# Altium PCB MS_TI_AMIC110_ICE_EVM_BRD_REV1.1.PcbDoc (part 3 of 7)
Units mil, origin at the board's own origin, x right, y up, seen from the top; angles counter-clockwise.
Board outline 3464.57 x 2204.72 mil, 8 copper layers (TopLayer - S1 (.GTL), MidLayer1 - S2 (.G1), MidLayer2 - S3 (.G2), MidLayer3 - S4 (.G3), MidLayer4 - S5 (.G4), MidLayer5 - S6 (.G5), MidLayer6 - S7 (.G6), BottomLayer - S8 (.GBL)), stack 58.937 mil thick; 504 components, 369 nets, 1811 pads, 874 vias.
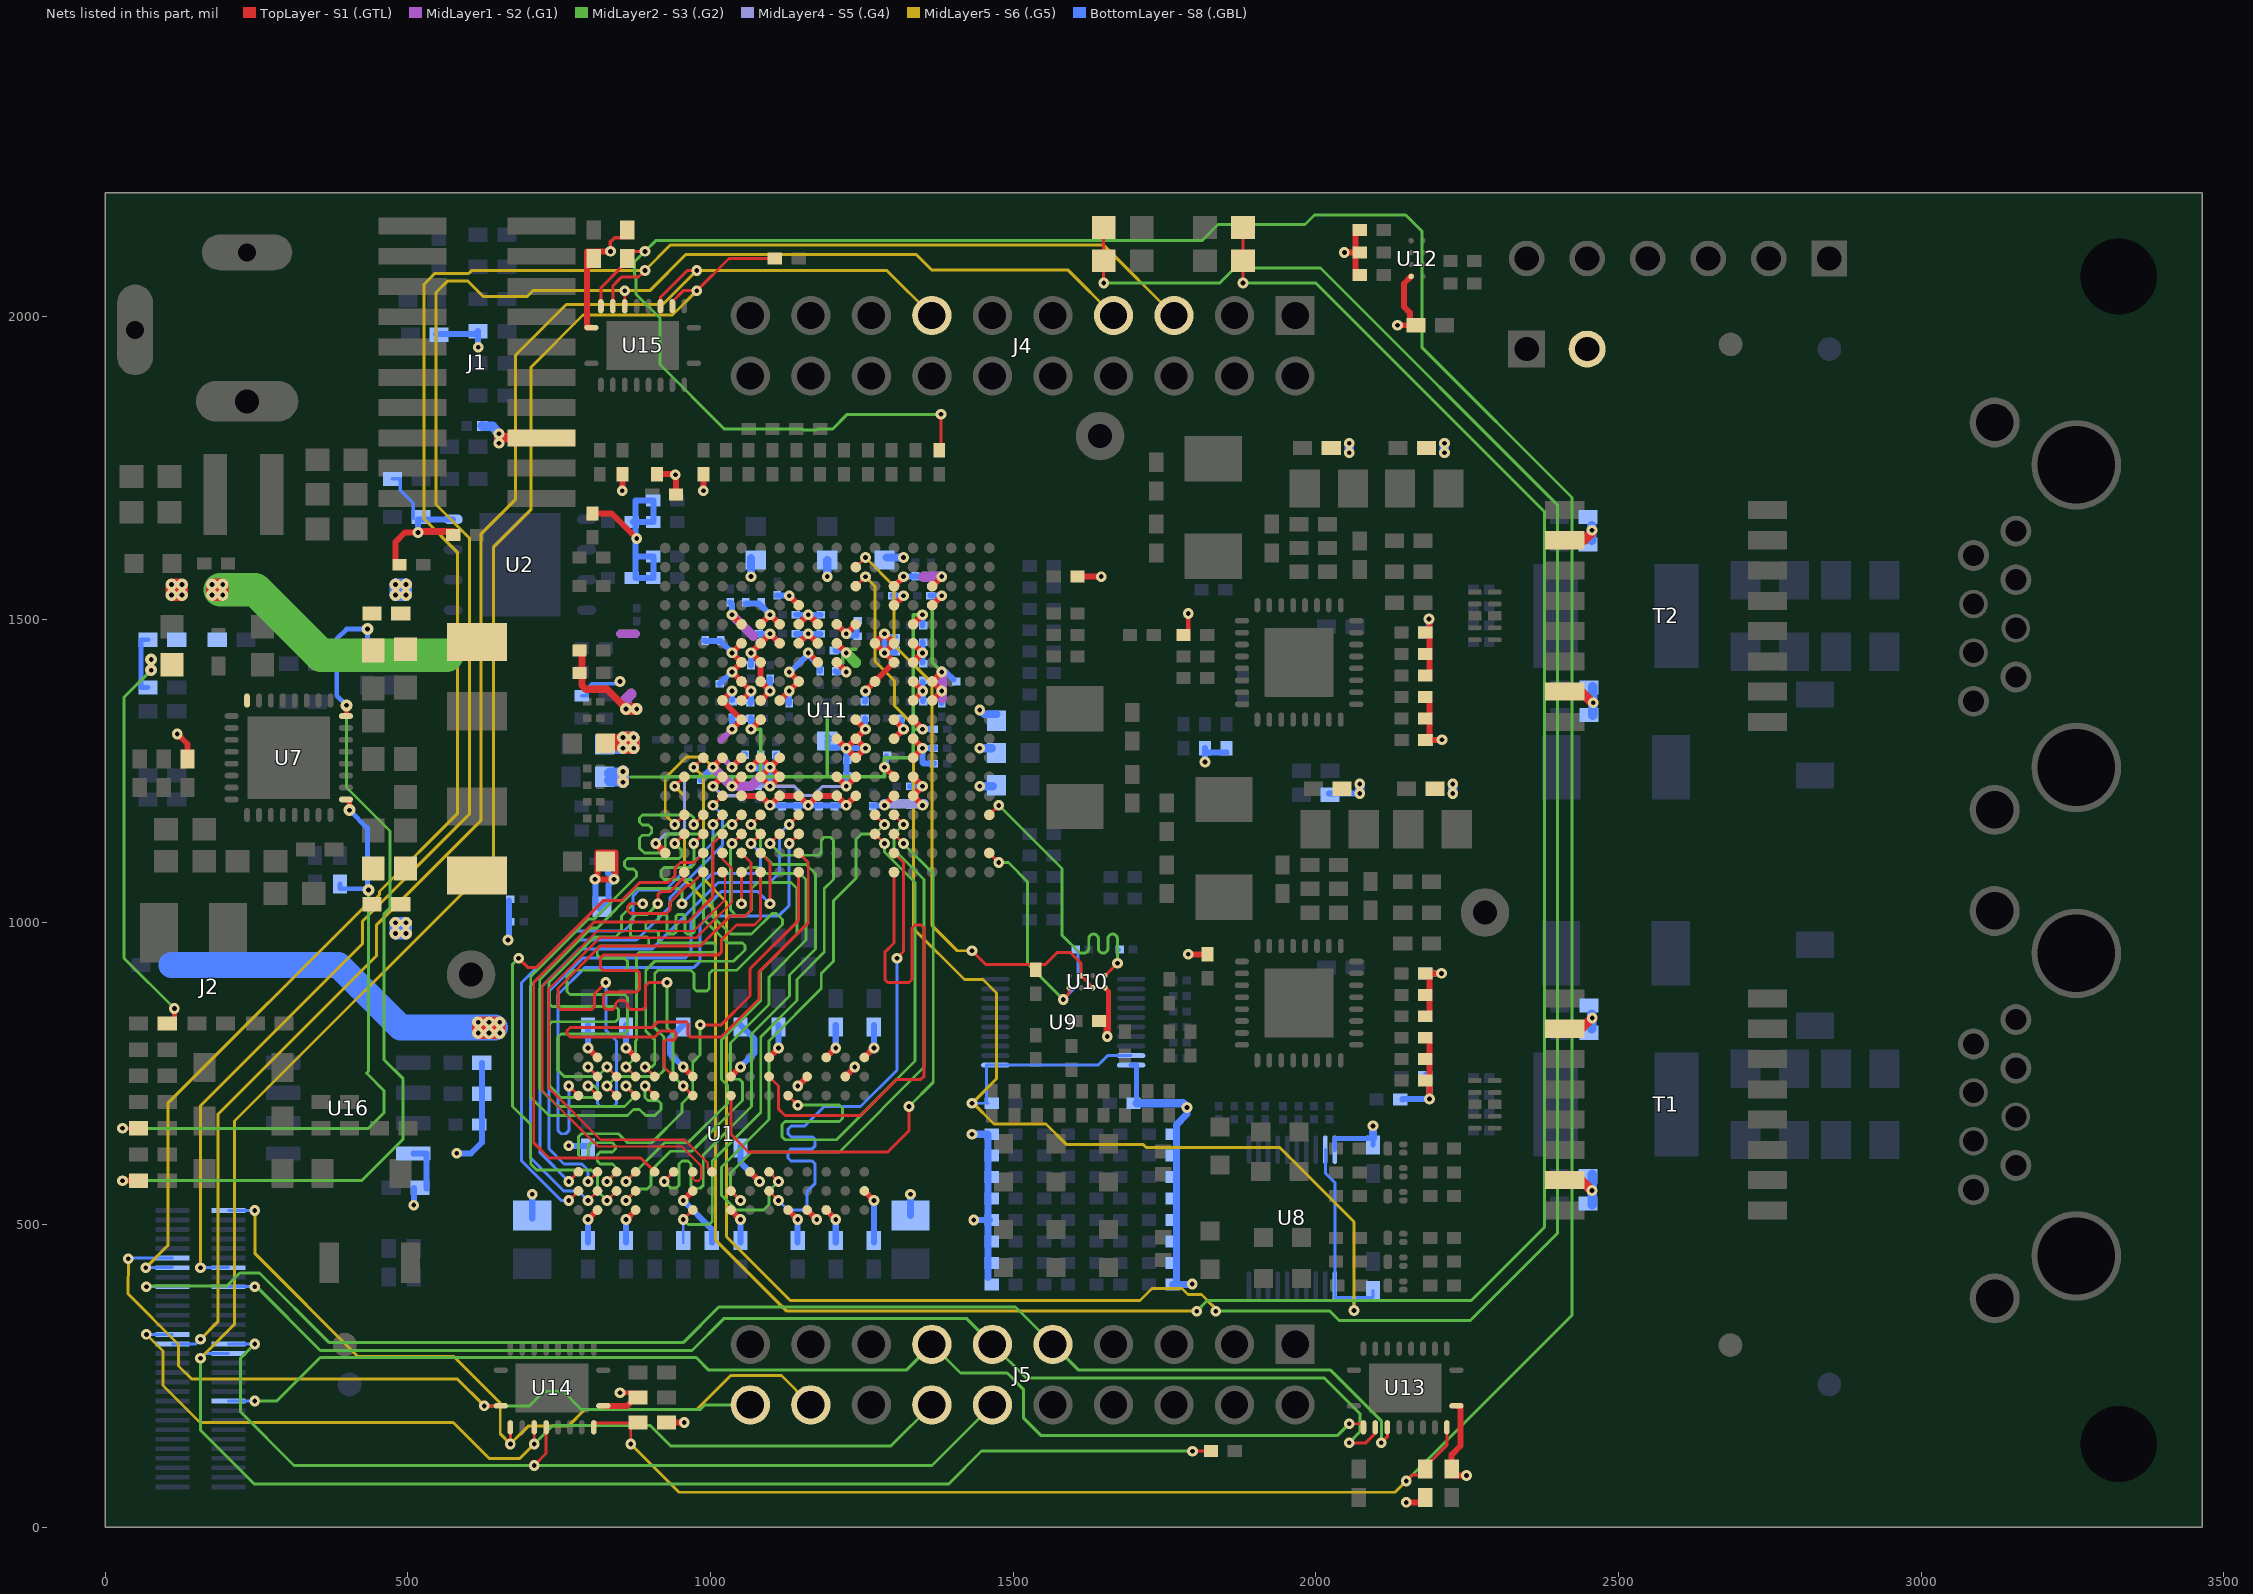
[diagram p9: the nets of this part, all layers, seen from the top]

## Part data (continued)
U16: "256 kb I2C CMOS Serial EEPROM, SOIC-8", Manufacturer="ON Semiconductor", Supplier Part Number 1=CAT24C256WI-GT3OSCT-ND
Y1 Y2 Y3: "Crystal, 25 MHz, 18 pF, SMD", Frequency="25 MHz", Frequency Stability=±20ppm, Manufacturer="CTS ELECTRONIC COMPONENTS", Supplier Part Number 1=445123D25M00000
ZZ1: library part AssemblyNoteLabel, Alternate Manufacturer=-
ZZ2 ZZ3 ZZ4: library part AssemblyNote, Alternate Manufacturer=-

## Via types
v1: diameter 17.72, hole 7.87, TopLayer - S1 (.GTL) to BottomLayer - S8 (.GBL), 746 vias
v2: diameter 19.68, hole 7.87, TopLayer - S1 (.GTL) to BottomLayer - S8 (.GBL), 128 vias

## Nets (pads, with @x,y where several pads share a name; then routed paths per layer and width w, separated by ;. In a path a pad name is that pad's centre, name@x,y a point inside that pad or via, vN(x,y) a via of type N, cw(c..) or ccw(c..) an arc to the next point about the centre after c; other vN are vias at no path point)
1V1: C147.1 C148.1 C149.1 C150.1 C151.1 C152.1 C153.1 C154.1 C155.1 C156.1 C157.1 C158.1 C159.1 C160.1 C161.1 C162.1 C163.1 C164.1 C165.1 C166.1 C167.1 R77.2 U11.A2 U11.D6 U11.F6 U11.F7 U11.F10 U11.F11 U11.F12 U11.F13 U11.G6 U11.G7 U11.G10 U11.G13 U11.H11 U11.H13 U11.J12 U11.J13 U11.K6 U11.K8 U11.K12 U11.L6 U11.L7 U11.L8 U11.L9 U11.M11 U11.M13 U11.N8 U11.N9 U11.N12 U11.N13 | length 2319.2
  TopLayer - S1 (.GTL) w10: v1(1003.94,1224.41) U11.D6@1019.68,1240.16 ; v1(1066.93,1255.91) U11.F7@1082.68,1271.65 v1(1098.43,1255.91) ; U11.F11@1082.68,1397.64 1085.63,1394.67 v1(1098.42,1381.88) U11.F10@1082.68,1366.14 U11.F10@1085.63,1369.11 ; U11.F11@1085.63,1394.68 U11.F11@1082.68,1397.64 U11.F12@1082.68,1429.13 v1(1066.93,1444.88) 1082.66,1460.64 v1(1098.43,1476.38) U11.G13@1114.17,1460.63 ; U11.G7@1114.17,1271.65 v1(1098.43,1255.91) ; U11.G10@1114.18,1366.16 v1(1129.92,1381.89) 1145.67,1397.64 v1(1129.92,1413.39) ; U11.H13@1145.68,1460.64 v1(1161.42,1476.38) U11.J13@1177.17,1460.63 ; v1(1161.42,1444.88) U11.J12@1177.17,1429.13 ; U11.K6@1208.66,1240.16 v1(1224.41,1224.41) U11.L6@1240.16,1240.16 ; U11.K8@1208.66,1303.15 v1(1224.41,1287.4) ; U11.K12@1208.66,1429.13 v1(1224.41,1413.39) ; U11.L9@1240.16,1334.65 v1(1255.91,1318.9) U11.L8@1240.16,1303.15 ; v1(1255.91,1381.89) U11.M11@1271.65,1397.64 U11.N12@1303.15,1429.13 v1(1287.4,1444.88) ; U11.N8@1303.15,1303.15 v1(1318.9,1318.9) U11.N9@1303.15,1334.65 ; v1(1098.43,1255.91) U11.G6@1114.17,1240.16 v1(1098.43,1224.41) U11.F6@1082.68,1240.16 v1(1098.43,1255.91) ; v1(1224.41,1287.4) U11.L8@1240.16,1303.15 ; v1(1224.41,1287.4) U11.L7@1240.16,1271.65 v1(1255.91,1287.4) U11.L8@1240.16,1303.15 ; v1(1287.4,1444.88) U11.M13@1271.65,1460.63 v1(1287.4,1476.38) U11.N13@1303.15,1460.63 v1(1287.4,1444.88)
  TopLayer - S1 (.GTL) w12: v1(909.45,1129.92) U11.A2@925.2,1114.17
  TopLayer - S1 (.GTL) w19.68: C162.1@826.77,1297.24 826.77,1301.18 855.31,1301.18 855.31,1293.31 C162.1@828.74,1293.31 ; v2(855.31,1287.4) v2(855.31,1305.12) v2(873.03,1305.12) v2(873.03,1287.4) v2(855.31,1287.4)
  MidLayer1 - S2 (.G1) w19.68: v2(873.03,1287.4) v2(873.03,1305.12)
  MidLayer4 - S5 (.G4) w4.92: v1(909.45,1129.92) 925.2,1145.67 947.83,1145.67 957.18,1155.02 957.18,1235.84 ; 1138.36,1224.41 1153.62,1209.15 1169.78,1209.15 1185.04,1224.41 v1(1224.41,1224.41)
  MidLayer4 - S5 (.G4) w5.91: v1(1003.94,1224.41) 1019.69,1208.66 1042.74,1208.66 1058.49,1224.41 v1(1098.43,1224.41) 1138.36,1224.41
  BottomLayer - S8 (.GBL) w9.84: C164.1@1066.93,1424.41 v1(1066.93,1444.88) ; C165.1@1077.95,1476.38 v1(1098.43,1476.38) ; C149.1@1078.74,1227.36 v1@1097.44,1227.36 ; v1(1098.43,1224.41) v1(1098.43,1255.91) ; v1(1098.42,1381.88) C163.1@1098.43,1402.36 ; C152.1@1129.92,1361.42 v1(1129.92,1381.89) ; v1(1129.92,1413.39) 1131.9,1413.4 1161.42,1442.91 1161.42,1441.93 1181.1,1422.24 C153.1@1181.1,1414.57 ; C166.1@1140.94,1476.38 C167.1@1181.89,1476.38 ; C148.1@1192.91,1299.21 1192.91,1288.39 1223.43,1288.39 v1(1224.41,1287.4) ; C148.1@1192.92,1307.4 C148.1@1197.17,1303.15 ; C154.1@1206.69,1414.57 1207.87,1413.39 v1(1224.41,1413.39) ; v1(1224.41,1224.41) v1(1224.41,1287.4) ; C156.1@1255.12,1336.61 1255.12,1319.69 v1(1255.91,1318.9) ; C155.1@1255.12,1364.17 1255.91,1364.96 v1(1255.91,1381.89) ; v1(1255.91,1287.4) v1(1224.41,1287.4) ; C158.1@1305.12,1446.06 1304.92,1445.87 1288.39,1445.87 v1(1287.4,1444.88) v1(1287.4,1476.38) 1292.32,1471.46 C157.1@1305.12,1471.46 ; v1@1315.94,1318.9 C159.1@1315.94,1334.65
  BottomLayer - S8 (.GBL) w10: 1082.68,1255.91 C150.1@1082.68,1276.38 ; v1(1098.43,1255.91) 1108.27,1265.75 C151.1@1108.27,1276.38
  BottomLayer - S8 (.GBL) w13.78: v1(1066.93,1255.91) v1(1098.43,1255.91)
  BottomLayer - S8 (.GBL) w19.68: C147.1@820.87,1287.4 v2(855.31,1287.4) ; C147.1@820.87,1299.21 v2@855.31,1299.21 ; v2@857.58,1292.32 v2@855.31,1292.32 ; v2(855.31,1287.4) v2@855.31,1292.32 ; v2(855.31,1287.4) v2(873.03,1287.4) v2(873.03,1305.12) v2(855.31,1305.12) v2@855.31,1299.21 ; v2@855.31,1292.32 v2@855.31,1299.21 ; v2(479.33,1540.35) v2(497.05,1540.35) v2(497.05,1558.07) v2(479.33,1558.07) v2(479.33,1540.35)
1V1_EN: C70.1 C71.1 L1.2 R77.1 R78.2 R95.2 U7.8 | length 1521.2
  TopLayer - S1 (.GTL) w7.87: U7.8@397.64,1340.55 398.62,1341.54 v2(398.62,1358.27)
  TopLayer - S1 (.GTL) w9.84: v1(28.54,572.83) R95.2@55.12,572.83
  MidLayer2 - S3 (.G2) w4.92: v1@26.57,572.83 v1(28.54,572.83) 423.23,572.83 492.13,641.73 492.13,741.14 460.63,772.64 460.63,1013.78 470.47,1023.62 470.47,1150.59 398.62,1222.44 v2(398.62,1358.27)
  BottomLayer - S8 (.GBL) w7.87: v2(398.62,1358.27) 382.54,1374.35 382.54,1468.17 398.62,1484.25 v2(433.07,1484.25) R78.2@433.07,1438.98
1V5: C7.1 C8.1 C9.1 C10.1 C11.1 C12.1 C13.1 C14.1 C15.1 C16.1 C17.1 C18.1 C19.1 C20.1 C21.1 C22.1 C136.1 C137.1 C138.1 C139.1 C140.1 C141.1 C142.1 C143.1 C144.1 R34.1 R37.1 R81.2 U1.A1 U1.A8 U1.B2 U1.C1 U1.C9 U1.D2 U1.D9 U1.E9 U1.F1 U1.G7 U1.H2 U1.H9 U1.K2 U1.K8 U1.N1 U1.N9 U1.R1 U1.R9 U11.E5 U11.F5 U11.G5 U11.H5 U11.J5 U11.K5 U11.L5 | length 2836.2
  TopLayer - S1 (.GTL) w10: v1(797.42,508.65) U1.R9@813.17,524.4 ; v1(797.42,792.15) U1.R1@813.17,776.4 ; v1(860.42,508.65) U1.N9@876.17,524.4 ; v1(860.42,792.15) U1.N1@876.17,776.4 ; v1(954.92,540.15) U1.K8@970.67,555.9 ; v1(954.92,760.65) U1.K2@970.67,744.9 ; U1.H9@1033.67,524.4 v1(1049.42,508.65) ; U1.H2@1033.67,744.9 v1(1049.42,760.65) ; U11.E5@1051.18,1208.66 U11.F5@1082.68,1208.66 v1(1098.43,1192.91) U11.G5@1114.17,1208.66 1145.67,1208.66 v1(1161.42,1192.91) U11.J5@1177.17,1208.66 U11.K5@1208.66,1208.66 v1(1224.41,1192.91) U11.L5@1240.16,1208.66 ; U1.G7@1065.17,587.4 v1(1080.92,571.65) ; U1.F1@1096.67,776.4 v1(1112.42,792.15) ; U1.E9@1128.17,524.4 v1(1143.92,508.65) ; v1(1143.92,729.15) U1.D2@1159.67,744.9 ; U1.D9@1159.67,524.4 v1(1175.42,508.65) ; U1.C9@1191.17,524.4 v1(1206.92,508.65) ; U1.C1@1191.17,776.4 v1(1206.92,792.15) ; U1.B2@1222.67,744.9 v1(1238.42,760.65) ; U1.A8@1254.17,555.92 v1(1269.92,540.15) ; U1.A1@1254.17,776.4 v1(1269.92,792.15) ; v1@812.92,1070.4 842.92,1070.4 842.92,1115.16 812.92,1115.16 812.92,1100.39 v1@812.92,1070.4
  TopLayer - S1 (.GTL) w19.68: v2(633.86,816.93) v2(633.86,834.65) ; v2(633.86,816.93) v2(616.14,816.93) v2(616.14,834.65) v2(633.86,834.65) ; v2(633.86,816.93) v2(651.57,816.93) v2(651.57,834.65) v2(633.86,834.65)
  BottomLayer - S8 (.GBL) w9.84: v1(1098.43,1192.91) v1(1161.42,1192.91) 1204.72,1192.91 v1(1224.41,1192.91)
  BottomLayer - S8 (.GBL) w10: v1(665.42,970.4) 667.32,972.3 C143.1@667.32,1035.43 ; C8.1@705.42,510.4 v1(705.42,550.4) ; v1(765.92,630.4) R37.1@797.42,630.4 ; C11.1@797.42,470.4 C11.1@797.42,474.02 v1(797.42,508.65) ; v1(797.42,792.15) C18.1@797.42,826.78 C18.1@797.42,830.4 ; v1@812.92,1070.4 810.04,1067.51 810.04,1029.53 816.93,1022.64 820.08,1025.79 831.69,1037.4 831.69,1062.01 v1(840.55,1070.87) 830.71,1080.71 C142.1@830.71,1100.4 ; C10.1@860.42,470.4 C10.1@860.42,474.02 v1(860.42,508.65) ; v1(860.42,792.15) C17.1@860.42,826.78 C17.1@860.42,830.4 ; v1(954.92,540.15) 1002.17,492.9 C9.1@1002.17,474.02 C9.1@1002.17,470.4 ; v1(954.92,760.65) 932.92,782.65 932.92,808.4 C16.1@954.92,830.4 ; C22.1@1049.42,470.4 C22.1@1049.42,474.02 v1(1049.42,508.65) ; R34.1@1049.42,630.4 R34.1@1049.42,626.78 1049.42,603.15 v1(1080.92,571.65) ; v1(1049.42,760.65) 1072.92,784.15 1072.92,806.9 C15.1@1049.42,830.4 ; v1(1112.42,792.15) C14.1@1112.42,826.78 C14.1@1112.42,830.4 ; C21.1@1143.92,470.4 C21.1@1143.92,474.02 v1(1143.92,508.65) ; C20.1@1206.92,470.4 C20.1@1206.92,474.02 v1(1206.92,508.65) ; v1(1206.92,792.15) C13.1@1206.92,826.78 C13.1@1206.92,830.4 ; C19.1@1269.92,470.4 C19.1@1269.92,474.02 v1(1269.92,540.15) ; v1(1269.92,792.15) C12.1@1269.92,826.78 C12.1@1269.92,830.4
  BottomLayer - S8 (.GBL) w11.81: C7.1@1330.42,515.4 v1(1330.42,550.4)
  BottomLayer - S8 (.GBL) w19.68: v2(633.86,816.93) 633.86,825.79 v2(633.86,834.65) ; v2(633.86,816.93) v2(616.14,816.93) 616.14,825.79 v2(616.14,834.65) v2(633.86,834.65) ; v2(633.86,816.93) v2(651.57,816.93) v2(651.57,834.65) v2(633.86,834.65)
  BottomLayer - S8 (.GBL) w43.31: R81.2@109.25,929.13 384.84,929.13 488.19,825.79 616.14,825.79 633.86,825.79 643.7,825.79
  other v1: 809.06,1070.87
1V8_1: C124.1 C125.1 C126.1 C127.1 C130.1 C134.1 C135.1 C146.1 R94.2 R182.1 R183.2 U11.D10 U11.E7 U11.E9 U11.H15 U11.N16 U11.R10 U11.R11 U11.R16 | length 995.1
  TopLayer - S1 (.GTL) w10: v1(1035.43,1255.91) U11.E7@1051.18,1271.65 ; v1(1035.43,1381.89) U11.D10@1019.68,1366.14 U11.E9@1051.18,1334.65 v1(1035.44,1318.9) ; v1(1129.92,1539.37) U11.H15@1145.68,1523.63 ; U11.N16@1303.15,1555.12 v1(1318.9,1570.87) ; U11.R10@1366.14,1366.14 1366.64,1366.15 v1(1381.89,1381.89) 1366.18,1397.64 v1(1381.89,1413.39) ; U11.R16@1366.14,1555.12 v1(1381.89,1570.87)
  TopLayer - S1 (.GTL) w11.81: R182.1@783.46,1448.82 787.4,1444.88 787.4,1415.35 R183.2@783.46,1411.42 787.4,1407.48 787.4,1390.75 793.31,1384.84 828.74,1384.84 860.24,1353.35 v2(860.24,1352.36)
  TopLayer - S1 (.GTL) w19.68: v2@118.11,1557.09 v2@118.11,1558.07 ; v2(860.24,1352.36) v2(877.95,1352.36) ; v2@118.11,1558.07 v2(109.25,1558.07) v2(109.25,1540.35) v2(126.97,1540.35) v2(126.97,1558.07) v2@118.11,1558.07
  MidLayer1 - S2 (.G1) w10: 1016.73,1274.61 v1(1035.43,1255.91) ; 1016.73,1300.19 v1(1035.44,1318.9)
  MidLayer1 - S2 (.G1) w13.78: 850.39,1476.38 876.97,1476.38
  MidLayer1 - S2 (.G1) w17.72: v2@860.24,1354.33 860.24,1368.11 869.09,1376.97 ; 1352.36,1570.87 v1(1381.89,1570.87) ; 1381.89,1371.06 v1(1381.89,1381.89) v1(1381.89,1413.39)
  MidLayer2 - S3 (.G2) w5.91: 1366.14,1526.57 1366.14,1502.21 1366.05,1502.12 1366.05,1453.59 1366.14,1453.49 1366.14,1429.13 v1(1381.89,1413.39)
  BottomLayer - S8 (.GBL) w9.84: v1(1035.44,1318.9) C130.1@1035.44,1338.59 ; C125.1@1035.43,1367.13 v1(1035.43,1381.89) ; C124.1@1109.25,1539.37 v1(1129.92,1539.37) ; v1(1318.9,1570.87) C126.1@1337.4,1570.87 ; C126.1@1338.58,1571.65 1339.37,1570.87 1345.37,1570.87 1345.48,1570.97 1357.27,1570.97 1357.38,1570.87 C127.1@1363.39,1570.87 ; C127.1@1364.17,1571.65 C127.1@1363.39,1570.87 ; v1(1381.89,1570.87) C127.1@1363.39,1570.87 ; v1(1381.89,1413.39) 1388.79,1413.38 C146.1@1401.57,1400.59
  BottomLayer - S8 (.GBL) w10: v1(1035.43,1255.91) C134.1@1056.5,1276.97 ; C135.1@1381.89,1362.2 v1(1381.89,1381.89)
  BottomLayer - S8 (.GBL) w17.72: v2(860.24,1352.36) v2(877.95,1352.36)
1V8_1_EN: C84.1 R87.2 R94.1 R96.2 U7.16 | length 742.3
  TopLayer - S1 (.GTL) w7.87: R87.2@114.17,829.72 v1(114.17,857.28)
  MidLayer2 - S3 (.G2) w4.92: v2(75.79,1416.34) 30.63,1371.18 30.63,1154.97 30.87,1154.73 30.87,1152.36 31,1152.23 31,1137.14 31.06,1137.09 31.06,940.4 v1(114.17,857.28)
  BottomLayer - S8 (.GBL) w7.87: R96.2@70.87,1387.8 59.06,1387.8 59.06,1466.54 R94.1@70.87,1466.54
  other v2: 75.79,1434.06
1V8_2: C116.1 C117.1 C118.1 C119.1 C120.1 C121.1 C122.1 C123.1 C145.1 R98.2 U11.B4 U11.D7 U11.E6 U11.E14 U11.F9 U11.K13 U11.N6 U11.P9 U11.P14 | length 2363.4
  TopLayer - S1 (.GTL) w4.92: v1(940.94,1161.42) U11.B4@956.69,1177.17
  TopLayer - S1 (.GTL) w10: v1(1003.94,1255.91) U11.D7@1019.68,1271.65 ; v1(1035.43,1224.41) U11.E6@1051.18,1240.16 ; v1(1035.42,1507.87) U11.E14@1051.18,1492.13 ; v1(1066.93,1318.9) U11.F9@1082.68,1334.65 ; U11.K13@1208.66,1460.63 v1(1224.41,1444.88) ; v1(1287.4,1255.91) U11.N6@1303.15,1240.16 ; U11.P9@1334.65,1334.65 v1(1350.39,1318.9) ; U11.P14@1334.65,1492.13 v1(1350.39,1507.87)
  TopLayer - S1 (.GTL) w19.68: 185.04,1552.17 v2@185.04,1558.07 ; v2@185.04,1558.07 v2(176.18,1558.07) v2(176.18,1540.35) v2(193.9,1540.35) v2(193.9,1558.07) v2@185.04,1558.07
  MidLayer1 - S2 (.G1) w15.75: v1(1003.94,1255.91) v1(1035.43,1224.41) 1066.93,1224.41 1082.68,1240.16 ; v1(1035.42,1507.87) 1070.87,1472.44
  MidLayer2 - S3 (.G2) w4.92: 867.92,1240.15 927.15,1240.15 956.69,1240.15
  MidLayer2 - S3 (.G2) w5.91: 925.2,1238.19 927.15,1240.15 1003.92,1240.16 ; v1(1003.94,1255.91) 1003.92,1240.16 ; v1(1035.43,1224.41) 1035.42,1240.15 ; v1(1066.93,1318.9) 1082.68,1318.9 1082.68,1240.16 ; 1192.92,1350.4 1192.92,1240.16 ; 1218.5,1428.15 1218.5,1444.88 v1(1224.41,1444.88) ; 1240.16,1450.79 v1@1224.41,1450.79 ; v1(1350.39,1318.9) 1334.65,1318.9 ; v1(1350.39,1507.87) 1334.65,1507.9 1334.65,1318.9 ; 1003.92,1240.16 1035.42,1240.16 ; 1035.42,1240.15 1082.66,1240.15 ; 1082.68,1240.16 1192.92,1240.16 ; 1192.92,1240.16 1287.42,1240.16 1287.42,1271.65 1334.65,1271.65 1334.65,1318.9 ; v1(1224.41,1444.88) v1@1224.41,1450.79 ; v1(1224.41,1444.88) v1@1224.41,1450.79
  MidLayer2 - S3 (.G2) w17.72: v1(1224.41,1444.88) 1240.16,1429.13
  MidLayer2 - S3 (.G2) w55.12: v2@189.96,1549.21 248.03,1549.21 356.3,1440.94 563.98,1440.94
  MidLayer4 - S5 (.G4) w19.68: v2(855.31,1231.3) v2(855.31,1249.02)
  MidLayer5 - S6 (.G5) w4.92: v1(940.94,1161.42) 925.2,1177.17 925.2,1238.19 959.65,1272.64 987.2,1272.64 v1(1003.94,1255.91)
  BottomLayer - S8 (.GBL) w9.84: v1@1035.43,1227.36 C116.1@1053.15,1227.36 ; v1(1066.93,1318.9) C119.1@1066.93,1337.6 ; C117.1@1206.69,1448.82 v1@1224.41,1448.82 ; v1@1290.35,1255.91 C121.1@1290.35,1273.62 ; v1(1350.39,1318.9) C118.1@1363.19,1318.9 ; C122.1@1350.39,1490.16 v1(1350.39,1507.87)
  BottomLayer - S8 (.GBL) w10: C120.1@1032.48,1528.35 1035.44,1525.39 v1(1035.42,1507.87)
  BottomLayer - S8 (.GBL) w11.81: C145.1@984.25,1235.43 1004.72,1255.91 v1(1003.94,1255.91)
  BottomLayer - S8 (.GBL) w19.68: C123.1@833.66,1234.25 v2@853.35,1234.25 ; C123.1@833.66,1246.06 v2@853.35,1246.06 ; v2(855.31,1231.3) v2(855.31,1249.02)
3V3: C1.2 C23.2 C24.2 C25.1 C26.2 C27.1 C40.1 C41.1 C42.1 C43.1 C47.2 C48.1 C49.2 C50.1 C59.1 C60.1 C61.1 C62.1 C88.1 C89.2 C90.2 C91.1 C92.1 C93.1 C94.2 C95.2 C96.2 C97.1 C98.1 C99.1 C100.2 C101.2 C102.2 C103.1 C104.1 C105.1 C106.2 C107.2 C108.2 C109.2 C110.2 C111.2 C112.2 C113.2 C114.2 C115.2 C128.1 C129.1 C172.2 C173.1 C174.1 C175.1 C176.2 J1.5 J9.2 R2.2 R11.2 R39.2 R40.2 R41.2 R42.2 R43.2 R44.2 R45.2 R46.2 R48.1 R53.2 R55.2 R57.2 R58.2 R59.2 R60.2 R61.2 R62.2 R64.2 R67.2 R68.2 R76.1 R89.2 R101.2 R103.2 R104.2 R105.2 R106.2 R107.2 R108.2 R109.2 R110.2 R111.2 R112.2 R113.2 R114.2 R115.2 R116.2 R117.2 R118.2 R138.2 R155.2 R162.1 R168.1 R171.1 R173.2 R174.1 R175.2 R190.2 R207.1 R208.1 R213.1 R214.1 R215.2 R216.1 R217.2 R218.2 R219.2 R237.1 R238.2 R239.2 R240.2 T1.2 T1.7 T2.2 T2.7 U2.8 U8.20 U9.20 U10.A2 U11.E10 U11.E11 U11.E12 U11.E13 U11.F14 U11.G14 U11.H14 U11.J14 U11.K14 U11.L14 U11.N5 U11.N15 U11.P5 U11.P6 U11.P7 U11.P8 U11.P10 U11.P11 U11.P12 U11.P13 U11.R15 U12.A2 U13.20 U14.20 U15.20 U16.8 | length 5687.2
  TopLayer - S1 (.GTL) w5.91: v1@834.65,2110.24 834.65,2124.02 841.54,2130.91 862.2,2130.91 R175.2@862.2,2143.7
  TopLayer - S1 (.GTL) w7.87: v1(850.39,222.44) C174.1@878.94,222.44 ; U10.A2@1651.57,891.73 1657.48,885.83 1657.48,829.72 ; R237.1@1789.37,1477.36 v1(1789.37,1509.84)
  TopLayer - S1 (.GTL) w9.84: v1(119.09,1311.02) 135.83,1294.29 R101.2@135.83,1269.69 ; R238.2@486.22,1590.55 479.33,1597.44 479.33,1627.95 495.08,1643.7 v1(516.73,1643.7) ; U15.20@803.15,1982.28 796.26,1982.28 796.26,2108.27 v1@831.69,2108.27 ; R239.2@805.12,1675.2 836.61,1675.2 v1(877.95,1633.86) ; U14.20@822.83,200.79 862.2,200.79 875.98,214.57 C174.1@879.92,214.57 ; v1(854.33,1712.6) R213.1@854.33,1740.16 ; R215.2@911.42,1740.16 942.91,1740.16 R214.1@942.91,1706.69 ; R174.1@927.17,173.23 v1(956.69,173.23) ; v1(988.19,1712.6) R216.1@988.19,1734.25 ; R155.2@1606.3,1570.87 v1(1645.67,1570.87) ; C90.2@1645.67,836.61 1655.51,836.61 ; v1(1789.37,946.85) R53.2@1820.87,946.85 ; v1(2047.24,2106.3) R55.2@2065.94,2106.3 ; R171.1@2072.83,2068.9 2065.94,2068.9 R55.2@2065.94,2106.3 ; R55.2@2072.83,2106.3 R55.2@2065.94,2106.3 ; R76.1@2072.83,2143.7 2065.94,2143.7 R55.2@2065.94,2106.3 ; v1(2134.84,1986.22) 2154.53,1986.22 2155.51,1985.24 2155.51,2006.89 2145.67,2016.73 2145.67,2055.12 U12.A2@2157.48,2066.93 ; v1(2149.61,41.34) 2173.23,41.34 R173.2@2181.1,49.21 ; U13.20@2232.28,200.79 2239.17,200.79 2239.17,134.84 2224.41,120.08 C173.1@2224.41,96.46 2224.41,85.63 v1(2249.02,85.63)
  TopLayer - S1 (.GTL) w10: v1(1035.43,1444.88) U11.E12@1051.18,1429.13 v1(1035.43,1413.39) U11.E11@1051.18,1397.64 v1(1066.93,1381.89) U11.E10@1051.18,1366.14 ; v1(1035.43,1444.88) U11.E13@1051.18,1460.63 ; U11.F14@1082.68,1492.13 v1(1098.43,1507.87) U11.G14@1114.17,1492.13 ; U11.H14@1145.68,1492.13 v1(1161.42,1507.87) U11.J14@1177.17,1492.13 ; U11.K14@1208.66,1492.13 v1(1224.41,1476.38) U11.L14@1240.16,1492.13 ; v1(1287.4,1192.91) U11.N5@1303.15,1208.66 ; U11.N15@1303.15,1523.62 v1(1318.9,1539.37) ; U11.P13@1334.57,1461.22 1334.57,1460.69 v1(1350.39,1444.88) ; U11.P6@1334.65,1240.16 v1(1350.39,1224.41) ; U11.P7@1334.65,1271.65 v1(1350.39,1287.4) U11.P8@1334.65,1303.15 ; U11.P10@1334.65,1366.14 v1@1350.4,1381.88 ; U11.P11@1334.77,1397.59 v1@1350.51,1381.85 ; v1(1350.39,1224.41) U11.P5@1334.65,1208.66 v1(1350.39,1192.91) ; U11.R15@1366.14,1523.62 v1(1381.89,1539.37) ; R44.2@2182.09,811.02 2187.99,811.02 2187.99,708.66 v1@2188.98,707.68 ; R43.2@2182.09,842.52 2187.99,842.52 2187.99,915.35 v1(2207.68,915.35) v1@2208.66,915.35 ; R60.2@2182.09,1374.02 2187.99,1374.02 2187.99,1301.18 v1(2208.66,1301.18) ; R59.2@2182.09,1405.51 2187.99,1405.51 C49.2@2187.99,1478.35 ; C49.2@2187.99,1480.31 v1@2187.99,1500.98
  TopLayer - S1 (.GTL) w11.81: v1@516.97,1643.21 519.76,1643.21 522.22,1645.67 574.8,1645.67 R240.2@574.8,1639.76 ; U11.P12@1334.65,1429.13 v1@1345.19,1439.68 ; v1(1655.51,811.02) 1655.51,836.61 1655.51,840.55
  TopLayer - S1 (.GTL) w15.75: v1(650.37,1791.36) v1@651.57,1808.07 ; 660.43,1800.2 J1.5@720.67,1800.2 ; T2.7@2386.42,1380.91 T2.7@2411.22,1380.91 2438.67,1380.91 v1@2455.8,1363.77 ; T1.7@2411.22,573.82 2438.4,573.82 v1@2455.67,556.55 ; T1.2@2440.34,825.48 v1@2457.71,842.86 ; T2.2@2443.2,1630.98 2456.2,1643.98 v1(2456.2,1647.57)
  MidLayer4 - S5 (.G4) w15.75: v1(1287.4,1192.91) 1287.4,1195.87 v1@1353.35,1195.87
  BottomLayer - S8 (.GBL) w5.91: R40.2@474.41,1732.28 487.2,1732.28 487.2,1713.58 508.86,1691.93 C23.2@508.86,1667.32 ; R138.2@787.4,1374.02 796.26,1374.02 796.26,1385.83 804.13,1393.7 847.44,1393.7 v1@851.38,1397.64
  BottomLayer - S8 (.GBL) w7.87: U9.20@1694.88,763.78 1703.74,763.78 C89.2@1703.74,700.79 ; U8.20@2031.5,624.02 2031.5,642.72 2094.49,642.72 C88.1@2094.49,631.89
  BottomLayer - S8 (.GBL) w9.84: U16.8@508.86,617.91 530.51,617.91 C176.2@530.51,560.04 ; v1(509.84,532.48) C176.2@509.84,561.02 ; v1(516.73,1643.7) 516.73,1665.55 U2.8@574.8,1665.55 ; v1(580.71,618.11) 604.33,618.11 622.05,635.83 R218.2@622.05,716.54 R219.2@622.05,767.72 ; R217.2@872.05,1661.42 875.98,1665.35 875.98,1696.85 R162.1@905.51,1696.85 R168.1@905.51,1661.42 875.98,1661.42 875.98,1635.83 v1@874.02,1633.86 ; R39.2@875.98,1568.9 875.98,1631.89 v1(877.95,1633.86) ; R39.2@876.97,1568.9 R208.1@905.51,1568.9 R207.1@905.51,1604.33 876.97,1604.33 ; C109.2@990.16,1465.35 990.94,1464.57 1016.32,1464.57 1034.65,1446.24 v1@1034.65,1444.88 ; C107.2@1014.96,1393.7 1034.65,1413.39 v1(1035.43,1413.39) ; C101.2@1140.94,1507.87 v1(1161.42,1507.87) C100.2@1181.89,1507.87 ; v1(1224.41,1476.38) 1227.39,1473.43 1241.14,1473.43 C104.1@1241.14,1495.08 ; C112.2@1266.73,1192.91 v1(1287.4,1192.91) ; C129.1@1300.39,1539.37 v1(1318.9,1539.37) ; C113.2@1329.72,1224.41 C113.2@1329.92,1224.41 v1(1350.39,1224.41) ; C114.2@1331.69,1192.91 v1(1350.39,1192.91) ; C94.2@1350.39,1396.65 1350.68,1381.46 C95.2@1350.68,1365.71 ; C97.1@1350.39,1429.13 v1(1350.39,1444.88) C98.1@1350.39,1462.6 ; C128.1@1363.39,1539.37 v1(1381.89,1539.37) ; C91.1@1368.9,1261.81 1352.21,1261.81 1350.4,1263.63 v1(1350.39,1287.4) C92.1@1370.86,1287.4 ; v1(1435.04,507.87) 1458.66,507.87 R109.2@1461.61,507.87 ; v1(1816.93,1264.76) R67.2@1816.93,1280.51 ; R67.2@1816.93,1287.4 R67.2@1816.93,1280.51 ; R68.2@1852.36,1280.51 R67.2@1816.93,1280.51 ; R64.2@2021.65,1212.6 v1(2072.83,1212.6)
  BottomLayer - S8 (.GBL) w10: R11.2@546.26,1971.46 611.22,1971.46 R2.2@616.14,1976.38 v1(616.14,1949.8) ; C111.2@1058.07,1526.57 1079.72,1526.57 v1(1098.43,1507.87) ; C106.2@1065.75,1362.2 1066.93,1363.39 v1(1066.93,1381.89) ; R48.1@2143.7,706.69 2143.7,707.68 v1(2187.99,707.68) ; C24.2@2181.1,915.35 v1(2207.68,915.35) ; C25.1@2182.09,748.03 2187.99,742.13 2187.99,708.66 v1@2188.98,707.68 ; C48.1@2182.09,1301.18 v1(2208.66,1301.18) ; C47.2@2187.01,1474.41 v1(2187.01,1500.98)
  BottomLayer - S8 (.GBL) w11.81: v1(1432.09,649.61) 1458.66,649.61 1458.66,507.87 1458.66,413.39 ; v1(1444.88,1350.39) 1451.77,1343.5 C99.1@1473.43,1343.5 ; R104.2@1763.78,401.57 1795.85,401.57 v1@1797.8,403.53 ; R104.2@1769.69,404.13 1769.69,665.35 1787.4,683.07 v1(1787.4,693.9)
  BottomLayer - S8 (.GBL) w13.78: v1(1066.93,1570.87) C115.2@1066.93,1601.38 ; v1(1192.91,1570.87) C102.2@1192.91,1598.43 ; C105.1@1291.34,1602.36 v1(1318.9,1602.36) ; v1(1444.88,1224.41) C93.1@1466.54,1224.41 ; v1(1444.88,1287.4) C96.2@1464.57,1287.4 ; C89.2@1703.74,700.79 1780.51,700.79 v1(1787.4,693.9) ; C88.1@2094.49,642.72 v1(2094.49,663.39)
  BottomLayer - S8 (.GBL) w15.75: C1.2@623.23,1819.88 624.02,1819.09 640.56,1819.09 v1(650.37,1807.11) v1(650.37,1791.36) ; v1(2055.12,1775.59) v1(2055.12,1791.34) ; v1(2072.83,1212.6) v1(2072.83,1228.35) ; v1@2212.6,1775.1 v1(2212.6,1775.59) v1(2212.6,1791.34) v1@2212.6,1791.83 ; v1(2226.38,1212.6) v1(2226.38,1228.35) ; C41.1@2456.3,823.82 v1@2456.3,848.03 ; C60.1@2456.3,1630.91 v1@2456.3,1655.12 ; v1@2456.42,559.44 C42.1@2456.42,583.65 ; C43.1@2456.74,533.34 v1@2456.74,555.59 ; C62.1@2457.35,1342.21 v1@2457.35,1364.45 ; v1@2457.35,1365.09 C61.1@2457.35,1389.31
  BottomLayer - S8 (.GBL) w19.68: v2(479.33,981.3) v2(479.33,999.02) v2(497.05,999.02) v2(497.05,981.3) v2(479.33,981.3)
  other v1: 1796,402 2456.31,556.77 2456.97,841.57 2458.32,1362.33 1350.49,1381.84 850.39,1397.64 941.93,1739.17 834.65,2108.27
3V3_EN: C80.1 C81.1 L3.2 R89.1 R90.2 R91.2 U7.1 | length 1071.4
  TopLayer - S1 (.GTL) w4.92: v1(28.54,659.45) R91.2@55.12,659.45
  TopLayer - S1 (.GTL) w7.87: U7.1@397.64,1202.76 403.54,1202.76 v2(403.54,1185.04)
  MidLayer2 - S3 (.G2) w4.92: v1@26.57,659.45 v1(28.54,659.45) 435.04,659.45 460.63,685.04 460.63,721.46 433.07,749.02 431.59,750.49 434.88,753.78 v2(434.88,1052.92)
  BottomLayer - S8 (.GBL) w7.87: R90.2@387.8,1062.99 387.8,1055.12 433.07,1055.12 433.07,1155.51 v2(403.54,1185.04)
AIN0: R180.2 R184.2 U11.B6 | length 4203.7
  TopLayer - S1 (.GTL) w4.92: v1(940.94,1224.41) U11.B6@956.69,1240.16 ; v1(1879.92,2056.1) R180.2@1879.92,2092.52 R184.2@1879.92,2147.64
  MidLayer2 - S3 (.G2) w4.92: v1(1803.15,357.28) 1820.87,375 2256.89,375 2377.95,496.06 2377.95,1678.15 2000,2056.1 v1(1879.92,2056.1)
  MidLayer5 - S6 (.G5) w4.92: v1(940.94,1224.41) 956.69,1208.66 956.69,1069.88 1007.87,1018.7 1007.87,475.39 1125.98,357.28 v1(1803.15,357.28)
AIN1: R181.2 R185.2 U11.C7 | length 4546.1
  TopLayer - S1 (.GTL) w4.92: v1(972.44,1255.91) U11.C7@988.19,1271.65 ; v1(1649.61,2056.1) R181.2@1649.61,2092.52 R185.2@1649.61,2147.64
  MidLayer2 - S3 (.G2) w4.92: v1(1649.61,2056.1) 1841.54,2056.1 1866.14,2080.71 2007.87,2080.71 2399.61,1688.98 2399.61,486.22 2254.92,341.54 2039.37,341.54 2023.62,357.28 v1(1834.65,357.28)
  MidLayer5 - S6 (.G5) w4.92: v1(972.44,1255.91) 988.19,1240.16 988.19,1071.85 1026.57,1033.46 1026.57,480.32 1131.89,375 1709.65,375 1729.33,394.68 1778.96,394.68 1788.87,384.78 1811.13,384.78 1820.4,375.51 ; 1820.33,375.44 1834.65,361.12 v1(1834.65,357.28)
AM_PHY1_LED1: R203.2 U10.D2 U11.V2 | length 419.3
  TopLayer - S1 (.GTL) w4.92: U11.V2@1460.63,1114.17 v1(1476.38,1098.43) ; v1@1582.68,873.03 1592.52,882.87 U10.D2@1592.52,891.73
  MidLayer2 - S3 (.G2) w4.92: v1(1476.38,1098.43) 1492.13,1098.43 1523.62,1066.93 1523.62,931.1 v1(1582.68,872.05)
  BottomLayer - S8 (.GBL) w4.92: v1(1582.68,872.05) 1607.28,896.65 1607.28,950.59 R203.2@1603.15,954.72
AM_PHY1_RXCLK: R206.2 U10.A1 U11.V4 | length 557
  TopLayer - S1 (.GTL) w4.92: U11.V4@1460.63,1177.17 v1(1476.38,1192.91) ; U10.A1@1651.57,911.42 v1(1672.24,932.09) 1672.48,932.32 v1@1672.48,932.68
  MidLayer2 - S3 (.G2) w4.68: v1(1476.38,1192.91) 1580.71,1088.58 1580.71,978.35 1610.24,948.82 1617.13,948.82 ; 1625,956.69 1625,972.44 ; 1640.75,956.69 1640.75,972.44 ; 1656.5,956.69 1656.5,972.44 ; v1(1672.24,932.09) 1672.24,972.44
  MidLayer2 - S3 (.G2) w4.92: 1617.13,948.82 ccw(c1617.13,956.69) 1622.33,950.79 ccw(c1617.13,956.69) 1625,956.69 ; 1625,972.44 cw(c1632.87,972.44) 1632.87,980.31 cw(c1632.87,972.44) 1640.75,972.44 ; 1640.75,956.69 ccw(c1648.62,956.69) 1648.62,948.82 ccw(c1648.62,956.69) 1656.5,956.69 ; 1656.5,972.44 cw(c1664.37,972.44) 1664.37,980.31 cw(c1664.37,972.44) 1672.24,972.44
  BottomLayer - S8 (.GBL) w4.92: v1(1672.24,932.09) 1672.24,950.98 R206.2@1675.98,954.72
BOOTCONFIG_DISABLE: R119.2 R120.2 U8.1 U8.19 U9.1 U9.19 U11.L16 | length 2577.9
  TopLayer - S1 (.GTL) w4.92: v1@1255.87,1570.86 U11.L16@1240.16,1555.12 v1@1255.91,1570.87
  MidLayer5 - S6 (.G5) w4.92: v1(1255.88,1570.85) 1271.65,1555.08 1271.65,1431.1 1303.64,1399.11 1303.64,1357.78 1335.14,1326.28 1335.14,989.67 1419.49,905.32 1450,905.32 1472.44,882.87 1472.44,741.14 1433.07,701.77 1468.5,666.34 1554.13,666.34 1587.6,632.87 1714.57,632.87 1719.49,627.95 1939.96,627.95 2062.99,504.92 v1(2062.99,358.27)
  BottomLayer - S8 (.GBL) w4.92: v1(1432.09,700.79) R120.2@1455.71,700.79 ; R120.2@1458.66,700.79 R120.2@1455.71,700.79 ; U9.19@1694.88,779.53 1656.5,779.53 1640.75,763.78 U9.1@1470.47,763.78 1455.71,763.78 R120.2@1455.71,700.79 ; U8.19@2015.75,624.02 2015.75,585.63 2031.5,569.88 U8.1@2031.5,399.61 2031.5,379.92 2062.99,379.92 ; v1(2062.99,358.27) 2062.99,379.92 ; R119.2@2094.49,391.73 2094.49,379.92 2062.99,379.92
BOOTCONFIG_FET_EN: R121.2 U10.B2 U10.C1 U11.L17 | length 1012.8
  TopLayer - S1 (.GTL) w4.92: U11.L17@1240.16,1586.61 v1(1255.91,1602.36) ; v1(1432.09,952.76) 1454.72,930.12 1553.15,930.12 1572.83,949.8 1594.49,949.8 1612.2,932.09 U10.C1@1612.2,911.42 U10.B2@1631.89,891.73
  MidLayer5 - S6 (.G5) w4.92: v1(1255.91,1602.36) 1303.15,1555.12 1303.15,1457.68 1366.14,1394.68 1366.14,994.09 1407.48,952.76 v1(1432.09,952.76)
BUS_ECAT_LATCH0: J2.44 J5.9 U13.14 | length 2309.2
  TopLayer - S1 (.GTL) w4.92: v1(2108.27,139.76) 2118.11,149.61 U13.14@2118.11,165.35
  MidLayer2 - S3 (.G2) w4.92: v1(67.91,397.64) 69.37,399.09 150.32,399.09 ; 150.35,399.11 164.61,399.11 201.06,399.09 222.24,420.28 254.92,420.28 370.08,305.12 954.72,305.12 1013.78,364.17 1503.94,364.17 J5.9@1565.75,302.36 1608.27,259.84 2024.61,259.84 2108.27,176.18 v1(2108.27,139.76)
  BottomLayer - S8 (.GBL) w4.92: v1(67.91,397.64) J2.44@111.22,397.64
BUS_ECAT_LATCH1: J2.43 J5.11 U13.13 | length 2116.4
  TopLayer - S1 (.GTL) w4.92: v1(2055.12,139.76) 2082.68,139.76 2098.43,155.51 U13.13@2098.43,165.35
  MidLayer2 - S3 (.G2) w4.92: v1(247.05,397.64) 248.52,399.11 355.32,292.32 969.49,292.32 1022.64,345.47 1422.64,345.47 J5.11@1465.75,302.36 1521.06,247.05 2013.78,247.05 2072.83,187.99 2072.83,157.48 v1(2055.12,139.76)
  BottomLayer - S8 (.GBL) w4.92: J2.43@203.74,397.64 v1(247.05,397.64)
BUS_ECAT_SYNC0: J2.48 J4.5 U15.18 | length 3320.3
  TopLayer - S1 (.GTL) w4.92: U15.18@838.58,2017.72 838.58,2047.24 838.43,2047.39 838.43,2051.25 848.45,2061.27 853.13,2065.94 880.91,2065.94 v1(891.73,2076.77)
  MidLayer5 - S6 (.G5) w4.92: v1(66.93,429.13) 103.35,465.55 103.35,700.79 437.28,1034.72 442.42,1034.72 453.08,1045.38 453.08,1050.53 581.69,1179.13 581.69,1611.22 526.57,1666.34 526.57,2054.13 544.29,2071.85 600.39,2071.85 605.32,2076.77 v1(891.73,2076.77) 934.06,2119.09 1649.02,2119.09 J4.5@1765.75,2002.36
  BottomLayer - S8 (.GBL) w4.92: v1(66.93,429.13) J2.48@111.22,429.13
BUS_ECAT_SYNC1: J2.47 J4.7 U15.17 | length 3098.4
  TopLayer - S1 (.GTL) w4.92: U15.17@858.27,2017.72 v1(858.27,2043.31)
  MidLayer5 - S6 (.G5) w4.92: v1(157.48,429.13) 157.48,696.85 425.2,964.57 425.2,1001.97 601.38,1178.15 601.38,1634.84 546.26,1689.96 546.26,2040.35 564.96,2059.06 599.41,2059.06 625,2033.46 696.85,2033.46 706.69,2043.31 v1(858.27,2043.31) 899.61,2043.31 959.65,2103.35 1339.57,2103.35 1365.16,2077.76 1590.35,2077.76 J4.7@1665.75,2002.36
  BottomLayer - S8 (.GBL) w4.92: v1(157.48,429.13) J2.47@203.74,429.13
BUS_FW_LOADED: J2.19 J5.13 U13.12 | length 2035.1
  TopLayer - S1 (.GTL) w4.92: v1(2055.12,171.26) 2078.74,171.26 U13.12@2078.74,165.35
  MidLayer2 - S3 (.G2) w4.92: v1(247.05,208.66) 283.46,208.66 355.32,280.51 976.38,280.51 997.05,259.84 1323.23,259.84 J5.13@1365.75,302.36 1413.19,254.92 1490.16,254.92 1516.73,228.35 1516.73,181.1 1546.26,151.57 2035.43,151.57 v1(2055.12,171.26)
  BottomLayer - S8 (.GBL) w4.92: J2.19@203.74,208.66 v1(247.05,208.66)
BUS_IRQ: J2.50 J5.20 U14.11 | length 1310.3
  TopLayer - S1 (.GTL) w4.68: v1(625.98,200.79) U14.11@653.54,200.79
  MidLayer2 - S3 (.G2) w4.92: v1(625.98,200.79) 700.79,200.79 724.41,224.41 756.89,224.41 786.42,194.88 983.27,194.88 990.75,202.36 J5.20@1065.75,202.36
  MidLayer5 - S6 (.G5) w4.92: v1(38.08,443.94) 37.4,385.83 121.06,302.17 121.06,266.73 142.72,245.08 581.69,245.08 v1(625.98,200.79)
  BottomLayer - S8 (.GBL) w4.92: v1@37.91,443.8 38.99,444.88 J2.50@111.22,444.88
BUS_SPI_D0: J2.31 J5.12 U14.15 | length 1556.9
  TopLayer - S1 (.GTL) w4.68: v1(708.66,102.36) 728.35,122.05 U14.15@728.35,165.35
  MidLayer2 - S3 (.G2) w4.92: v1(247.05,303.15) 223.43,279.53 223.43,190.94 312.01,102.36 v1(708.66,102.36) 1365.75,102.36 J5.12@1465.75,202.36
  BottomLayer - S8 (.GBL) w4.92: J2.31@203.74,303.15 v1(247.05,303.15)
BUS_SPI_D1_MCASP1_AFSX_MFSRB: J2.34 J5.14 U14.14 | length 1551.2
  TopLayer - S1 (.GTL) w4.68: v1(708.66,137.8) U14.14@708.66,165.35
  MidLayer2 - S3 (.G2) w4.92: v1(708.66,137.8) 739.17,168.31 900.59,168.31 934.06,134.84 1298.23,134.84 J5.14@1365.75,202.36
  MidLayer5 - S6 (.G5) w4.92: v1(67.91,318.9) 95.47,291.34 95.47,234.25 156.5,173.23 574.8,173.23 633.86,114.17 685.04,114.17 v1(708.66,137.8)
  BottomLayer - S8 (.GBL) w4.92: v1(67.91,318.9) J2.34@111.22,318.9
BUS_SPICLK: J2.32 J4.13 U15.14 | length 2760.6
  TopLayer - S1 (.GTL) w4.92: U15.14@917.32,2017.72 917.32,2032.48 961.61,2076.77 v1(977.36,2076.77)
  MidLayer5 - S6 (.G5) w4.92: v1(157.48,311.02) 186.02,339.57 186.02,682.09 447.83,943.9 447.83,995.08 621.06,1168.31 621.06,1641.73 678.15,1698.82 678.15,1937.01 761.81,2020.67 921.26,2020.67 v1(977.36,2076.77) 1291.34,2076.77 J4.13@1365.75,2002.36
  BottomLayer - S8 (.GBL) w4.92: J2.32@111.22,303.15 149.61,303.15 v1(157.48,311.02)
BUS_SPICS: J2.29 R186.2 R187.1 U15.13 | length 4293.4
  TopLayer - S1 (.GTL) w4.92: U15.13@937.01,2017.72 937.01,2025.59 954.72,2043.31 v1(977.36,2043.31) 1030.51,2096.46 R187.1@1106.3,2096.46 ; v1(1796.26,125.98) R186.2@1826.77,125.98
  MidLayer2 - S3 (.G2) w4.68: v1(157.48,279.53) 157.48,160.43 246.06,71.85 1393.7,71.85 1447.83,125.98 v1(1796.26,125.98)
  MidLayer5 - S6 (.G5) w4.92: v1(157.48,279.53) 213.58,335.63 213.58,671.26 641.73,1099.41 641.73,1620.08 703.74,1682.09 703.74,1917.32 789.37,2002.95 937.01,2002.95 v1(977.36,2043.31)
  BottomLayer - S8 (.GBL) w4.92: v1(157.48,279.53) 165.35,287.4 J2.29@203.74,287.4
BUS_SWITCH_ENABLE: R173.1 R174.2 R175.1 R179.2 U13.19 U14.19 U15.19 | length 6059.3
  TopLayer - S1 (.GTL) w4.68: U14.19@807.09,165.35 807.09,172.24 868.11,172.24 v1(868.11,137.8)
  TopLayer - S1 (.GTL) w4.92: U15.19@818.9,2017.72 818.9,2048.23 854.33,2083.66 R175.1@854.33,2096.46 ; R175.1@856.3,2108.27 v1@887.8,2108.27 ; R179.2@1377.95,1779.53 1381.89,1783.46 1380.7,1784.66 v1(1380.7,1839.07) ; v1(2149.61,76.77) 2159.45,86.61 R173.1@2178.15,86.61 ; R173.1@2181.1,96.46 2181.1,100.39 2216.54,135.83 U13.19@2216.54,165.35
  MidLayer2 - S3 (.G2) w4.92: v1(1380.7,1839.07) 1225.88,1839.07 1201.77,1814.96 1176.56,1814.96 1174.58,1812.98 1152.97,1812.98 1150.99,1814.96 1022.64,1814.96 916.34,1921.26 916.34,1998.03 876.79,2037.58 876.79,2067.36 874.51,2069.64 874.51,2083.91 874.56,2083.96 874.56,2091.1 v1(891.73,2108.27) 909.45,2125.98 1812.01,2125.98 1838.58,2152.56 1982.28,2152.56 1998.03,2168.31 2148.62,2168.31 2175.2,2141.73 2175.2,1949.8 2423.23,1701.77 2423.23,350.39 v1(2149.61,76.77)
  MidLayer5 - S6 (.G5) w4.92: v1(868.11,137.8) 947.83,58.07 2130.91,58.07 v1(2149.61,76.77)
BUS_SYS_RESETN: J2.59 J5.18 U14.12 | length 1287.9
  TopLayer - S1 (.GTL) w4.68: v1(669.29,137.8) U14.12@669.29,165.35
  MidLayer5 - S6 (.G5) w4.92: v1(247.05,523.62) 247.05,452.76 417.32,282.48 575.79,282.48 652.56,205.71 652.56,154.53 v1(669.29,137.8) 698.82,167.32 764.76,167.32 792.32,194.88 977.36,194.88 1033.46,250.98 1117.13,250.98 J5.18@1165.75,202.36
  BottomLayer - S8 (.GBL) w4.92: J2.59@203.74,523.62 v1(247.05,523.62)
DDR_A0: U1.N3 U11.F3 | length 942.6
  TopLayer - S1 (.GTL) w4.92: v1(860.42,729.15) U1.N3@876.17,713.4 ; v1@1067.46,1129.39 1067.46,1130.45 U11.F3@1082.68,1145.67
  MidLayer2 - S3 (.G2) w4.68: v1(860.42,729.15) 872.92,716.65 872.92,710.4 857.92,695.4 747.92,695.4 717.92,725.4 717.92,905.4 802.92,990.4 812.92,990.4 877.92,1055.4 947.92,1055.4 952.92,1050.4 v1(952.93,1030.41)
  BottomLayer - S8 (.GBL) w4.92: v1(952.93,1030.41) 1002.92,1080.4 1072.92,1080.4 1082.92,1090.4 1082.92,1113.9 v1(1066.93,1129.92)
DDR_A1: U1.P7 U11.H1 | length 946.7
  TopLayer - S1 (.GTL) w4.92: v1(828.92,571.65) U1.P7@844.67,587.4 ; v1(982.92,830.4) 1017.92,830.4 1065.42,877.9 1065.42,922.9 1145.68,1003.16 U11.H1@1145.68,1082.68
  MidLayer2 - S3 (.G2) w4.68: v1(828.92,571.65) 842.92,585.65 842.92,595.4 837.92,600.4 817.92,600.4 812.92,605.4 812.92,615.4 817.92,620.4 837.92,620.4 842.92,625.4 842.92,630.4 837.92,635.4 802.92,635.4 797.92,630.4 797.92,615.4 792.92,610.4 786.91,610.4 781.91,615.4 781.91,645.4 786.91,650.4 847.92,650.4 862.92,635.4 902.92,635.4 952.92,685.4 952.92,700.4 970.68,718.16 970.68,768.41 982.67,780.4 v1@982.67,830.15
DDR_A2: U1.P3 U11.E4 | length 941.7
  TopLayer - S1 (.GTL) w4.92: v1(828.92,729.15) U1.P3@844.67,713.4 ; v1(1035.43,1161.42) U11.E4@1051.18,1177.17
  MidLayer2 - S3 (.G2) w4.68: v1(828.92,729.15) 844.66,744.89 912.41,744.89 922.92,755.4 922.92,810.4 907.92,825.4 907.92,915.4 912.92,920.4 967.92,920.4 972.92,915.4 972.92,890.4 976.93,886.39 993.91,886.39 997.92,890.4 997.92,915.4 1002.92,920.4 1042.92,920.4 1118.67,996.15 1118.67,1004.65 1108.96,1014.36 1101.88,1014.36 1067.92,980.4 1032.92,980.4 1002.92,1010.4 1002.92,1137.79 1026.53,1161.4 v1(1035.43,1161.42)
DDR_A3: U1.N2 U11.C3 | length 943.5
  TopLayer - S1 (.GTL) w4.92: v1(860.42,760.65) U1.N2@876.17,744.9 ; v1(972.44,1129.92) U11.C3@988.19,1145.67
  MidLayer2 - S3 (.G2) w4.68: v1(860.42,760.65) 876.16,776.39 876.16,803.64 877.92,805.4 877.92,945.4 882.92,950.4 1004.92,950.4 1007.92,953.4 1007.92,962.4 1004.92,965.4 916.91,965.4 913.91,968.4 913.91,982.4 910.91,985.4 895.92,985.4 892.92,988.4 892.92,997.4 895.92,1000.4 910.91,1000.4 913.91,1003.4 913.91,1009.9 916.91,1012.9 924.92,1012.9 927.92,1009.9 927.92,983.4 930.92,980.4 939.92,980.4 942.92,983.4 942.92,1009.9 945.92,1012.9 954.92,1012.9 957.92,1009.9 957.92,983.4 960.92,980.4 969.42,980.4 972.42,983.4 972.42,1065.4 967.42,1070.4 922.92,1070.4 917.92,1075.4 917.92,1085.4 922.92,1090.4 967.42,1090.4 972.42,1095.4 v1(972.44,1129.92)
DDR_A4: U1.P8 U11.C2 | length 941.1
  TopLayer - S1 (.GTL) w4.92: v1(682.92,940.4) 697.92,925.4 712.92,925.4 822.92,1035.4 852.92,1035.4 882.92,1065.4 930.02,1065.4 941.07,1076.45 941.07,1089.15 950.47,1098.55 972.57,1098.55 U11.C2@988.19,1114.17 ; v1(828.92,540.15) U1.P8@844.67,555.9
  MidLayer2 - S3 (.G2) w4.68: v1(682.92,940.4) 672.92,930.4 672.92,695.4 702.92,665.4 702.92,600.4 712.92,590.4 802.92,590.4 813.16,580.16 813.16,555.91 v1(828.92,540.15)
DDR_A5: U1.P2 U11.B1 | length 942.8
  TopLayer - S1 (.GTL) w4.92: v1(828.92,760.65) U1.P2@844.67,744.9 ; v1(912.92,1030.4) 912.92,1045.4 917.92,1050.4 932.92,1050.4 956.7,1074.18 U11.B1@956.69,1082.68
  MidLayer2 - S3 (.G2) w4.68: v1(828.92,760.65) 813.18,744.91 758.41,744.91 747.92,755.4 747.92,810.4 752.92,815.4 857.92,815.4 862.92,820.4 862.92,875.4 857.92,880.4 767.92,880.4 762.92,885.4 762.92,910.4 772.92,920.4 857.92,920.4 862.92,925.4 862.92,935.4 857.92,940.4 817.92,940.4 812.92,945.4 812.92,955.4 817.92,960.4 894.92,960.4 897.92,963.4 897.92,972.4 894.92,975.4 870.92,975.4 867.92,978.4 867.92,1003.15 877.67,1012.9 895.42,1012.9 v1(912.92,1030.4)
DDR_A6: U1.R8 U11.D5 | length 947
  TopLayer - S1 (.GTL) w4.92: v1(797.42,540.15) U1.R8@813.17,555.9 ; v1(1003.94,1192.91) U11.D5@1019.68,1208.66
  BottomLayer - S8 (.GBL) w4.92: v1(797.42,540.15) 781.66,555.91 757.41,555.91 702.92,610.4 702.92,895.4 777.92,970.4 877.92,970.4 932.92,1025.4 932.92,1040.4 1019.66,1127.14 1019.66,1177.16 v1(1003.94,1192.91)
DDR_A7: U1.R2 U11.E2 | length 947.8
  TopLayer - S1 (.GTL) w4.92: v1(797.42,760.65) U1.R2@813.17,744.9 ; v1(826.93,900.4) 807.92,881.39 807.92,860.4 802.92,855.4 752.92,855.4 747.92,860.4 747.92,890.4 817.92,960.4 982.92,960.4 1032.92,1010.4 1057.92,1010.4 1066.95,1019.43 1066.95,1098.42 U11.E2@1051.18,1114.17
  BottomLayer - S8 (.GBL) w4.92: v1(797.42,760.65) 813.16,744.91 813.16,700.4 818.16,695.4 839.66,695.4 844.66,700.4 844.66,803.66 826.93,821.39 v1(826.93,900.4)
DDR_A8: U1.T8 U11.D4 | length 911.5
  TopLayer - S1 (.GTL) w4.92: v1(765.92,540.15) U1.T8@781.67,555.9 ; v1(1003.94,1161.42) U11.D4@1019.68,1177.17
  BottomLayer - S8 (.GBL) w4.92: v1(765.92,540.15) 753.17,540.15 687.92,605.4 687.92,900.4 772.92,985.4 857.18,985.4 872.18,1000.4 872.18,1043.44 881.8,1053.06 925.58,1053.06 1003.92,1131.4 v1(1003.94,1161.42)
DDR_A9: U1.R3 U11.C1 | length 946.7
  TopLayer - S1 (.GTL) w4.92: v1(797.42,729.15) U1.R3@813.17,713.4 ; v1(887.92,1030.4) 867.53,1030.4 862.92,1025.79 862.92,1019.27 867.53,1014.66 927.18,1014.66 932.92,1020.4 932.92,1032.66 960.66,1060.4 965.92,1060.4 U11.C1@988.19,1082.68
  MidLayer2 - S3 (.G2) w4.68: v1(797.42,729.15) 807.92,729.15 812.92,724.15 812.92,715.4 807.92,710.4 752.92,710.4 732.92,730.4 732.92,830.4 737.92,835.4 842.92,835.4 847.92,840.4 847.92,855.4 842.92,860.4 737.92,860.4 732.92,865.4 732.92,900.4 807.92,975.4 842.92,975.4 852.92,985.4 852.92,1010.4 872.92,1030.4 v1(887.92,1030.4)
DDR_A10: U1.L7 U11.F4 | length 943
  TopLayer - S1 (.GTL) w4.92: v1(923.42,571.65) U1.L7@939.17,587.4 ; v1(1066.93,1161.42) U11.F4@1082.68,1177.17
  MidLayer2 - S3 (.G2) w4.68: v1(923.42,571.65) 934.67,560.4 942.92,560.4 947.92,565.4 947.92,600.4 952.92,605.4 962.92,605.4 967.92,600.4 967.92,565.4 972.92,560.4 982.92,560.4 987.92,565.4 987.92,615.4 1067.92,695.4 1067.92,815.4 1130.42,877.9 1130.42,912.9 1173.17,955.65 1173.17,1080.15 1157.92,1095.4 1102.92,1095.4 1082.68,1115.64 1082.68,1145.64 v1(1066.93,1161.42)
DDR_A11: U1.R7 U11.F2 | length 941.7
  TopLayer - S1 (.GTL) w4.92: v1(797.42,571.65) U1.R7@813.17,587.4 ; U11.F2@1082.68,1114.17 1098.45,1098.41 v1(1098.42,1030.4)
  BottomLayer - S8 (.GBL) w4.92: v1(797.42,571.65) 797.42,590.4 787.42,600.4 757.92,600.4 732.92,625.4 732.92,885.4 787.92,940.4 957.92,940.4 967.92,950.4 967.92,1000.4 1017.92,1050.4 1078.42,1050.4 v1(1098.42,1030.4)
DDR_A12: U1.N7 U11.E3 | length 948.2
  TopLayer - S1 (.GTL) w4.92: v1(860.42,571.65) U1.N7@876.17,587.4 ; v1(1035.43,1129.92) U11.E3@1051.18,1145.67
  MidLayer2 - S3 (.G2) w4.68: v1(860.42,571.65) 924.17,635.4 962.92,635.4 1027.92,700.4 1027.92,730.4 1018.17,740.15 1018.17,805.65 1082.92,870.4 1082.92,920.4 1142.92,980.4 1142.92,1055.4 1132.92,1065.4 1077.92,1065.4 1067.92,1055.4 1067.92,1020.4 1057.92,1010.4 1042.92,1010.4 1032.92,1020.4 1032.92,1127.4 v1(1035.43,1129.92)
DDR_A13: U1.T3 U11.H3 | length 947.1
  TopLayer - S1 (.GTL) w4.92: v1(765.92,729.15) U1.T3@781.67,713.4 ; v1(1129.92,1129.92) 1130.56,1129.92 U11.H3@1146.62,1145.98
  BottomLayer - S8 (.GBL) w4.92: v1(765.92,729.15) 765.92,655.4 760.92,650.4 752.92,650.4 747.92,655.4 747.92,880.4 792.92,925.4 972.92,925.4 982.92,935.4 982.92,995.4 997.92,1010.4 1112.92,1010.4 1129.92,1027.4 v1(1129.92,1129.92)
DDR_A14: U1.T7 U11.H4 | length 940.8
  TopLayer - S1 (.GTL) w4.92: v1(765.92,571.65) U1.T7@781.67,587.4 ; v1@1132.82,1163.9 1132.82,1164.32 U11.H4@1145.67,1177.17
  BottomLayer - S8 (.GBL) w4.92: v1(765.92,571.65) 717.92,619.65 717.92,890.4 782.92,955.4 902.92,955.4 1012.92,1065.4 1097.92,1065.4 1114.16,1081.64 1114.16,1146.64 v1@1128.92,1161.4
  other v1: 1129.92,1161.42
DDR_A15: U1.M7 U11.D3 | length 949.8
  TopLayer - S1 (.GTL) w4.92: U1.M7@907.67,587.4 884.67,610.4 732.92,610.4 707.92,635.4 707.92,900.4 807.92,1000.4 962.92,1000.4 1003.83,1041.31 1003.83,1129.82 U11.D3@1019.68,1145.67
DDR_BA0: U1.M2 U11.C4 | length 948.3
  TopLayer - S1 (.GTL) w4.92: v1(891.92,760.65) U1.M2@907.67,744.9 ; v1(972.44,1161.42) U11.C4@988.19,1177.17
  MidLayer2 - S3 (.G2) w4.68: v1(891.92,760.65) 902.92,760.65 907.92,765.65 907.92,805.4 892.92,820.4 892.92,920.4 907.92,935.4 1037.92,935.4 1056.71,954.19 1056.71,961.61 1052.92,965.4 1027.92,965.4 988.41,1004.91 988.41,1140.66 983.41,1145.66 930.11,1145.66 925.2,1140.75 925.2,1123.03 916.34,1114.17 890.75,1114.17 882.87,1122.05 882.87,1138.78 887.8,1143.7 898.62,1143.7 902.92,1148 902.92,1155.12 897.64,1160.4 887.82,1160.4 882.92,1165.3 882.92,1172.24 887.82,1177.14 967.42,1177.14 972.42,1172.14 v1(972.44,1161.42)
DDR_BA1: U1.N8 U11.E1 | length 948.5
  TopLayer - S1 (.GTL) w4.92: v1(860.42,540.15) U1.N8@876.17,555.9 ; v1(1051.19,1030.4) U11.E1@1051.18,1082.68
  MidLayer2 - S3 (.G2) w4.68: v1(860.42,540.15) 879.29,559.02 895.41,559.02 901.79,565.4 901.79,589.27 934.04,621.52 969.04,621.52 1052.92,705.4 1052.92,735.4 1047.92,740.4 1037.92,740.4 1032.92,745.4 1032.92,800.4 1096.43,863.91 1096.43,908.91 1157.92,970.4 1157.92,1070.4 1147.92,1080.4 1087.92,1080.4 1077.92,1090.4 1062.92,1090.4 1051.19,1078.67 v1(1051.19,1030.4)
DDR_BA2: U1.M3 U11.B3 | length 949.4
  TopLayer - S1 (.GTL) w4.92: v1(891.92,729.15) U1.M3@907.67,713.4 ; v1(940.94,1129.92) U11.B3@956.69,1145.67
  MidLayer2 - S3 (.G2) w4.68: v1(891.92,729.15) 891.92,710.4 896.92,705.4 912.92,705.4 917.92,700.4 917.92,690.4 907.92,680.4 892.92,680.4 882.92,690.4 872.92,690.4 862.92,680.4 732.92,680.4 702.92,710.4 702.92,910.4 797.92,1005.4 807.92,1005.4 877.92,1075.4 877.92,1082.9 872.92,1087.9 862.92,1087.9 857.92,1092.9 857.92,1100.4 862.92,1105.4 947.92,1105.4 952.92,1110.4 952.92,1117.9 v1(940.94,1129.92)
DDR_CASN: U1.K3 U11.F1 | length 943.2
  TopLayer - S1 (.GTL) w4.92: v1(927.92,900.4) 897.92,900.4 892.92,895.4 892.92,860.4 887.92,855.4 867.92,855.4 862.92,860.4 862.92,865.4 857.92,870.4 847.92,870.4 842.92,865.4 842.92,860.4 837.92,855.4 827.92,855.4 822.92,860.4 822.92,879.66 827.92,884.66 877.92,884.66 882.92,889.66 882.92,915.4 877.92,920.4 822.92,920.4 817.92,925.4 817.92,940.4 822.92,945.4 1012.92,945.4 1017.92,950.4 1017.92,970.4 1042.92,995.4 1072.68,995.4 1082.68,1005.4 U11.F1@1082.68,1082.68 ; v1(954.92,729.15) U1.K3@970.67,713.4
  MidLayer2 - S3 (.G2) w4.68: v1(927.92,900.4) 927.92,825.4 937.92,815.4 937.92,746.15 v1(954.92,729.15)
DDR_CK: U1.J7 U11.D2 | length 944.6
  TopLayer - S1 (.GTL) w3.98: U1.J7@1002.17,587.4 995.7,593.87 995.7,601.62 956.92,640.4 818.48,640.4 732.92,725.96 732.92,889.84 817.48,974.4 976.92,974.4 1035.43,1032.91 1035.43,1088.58 1019.69,1104.33 U11.D2@1019.68,1114.17
DDR_CKE: R36.2 U1.K9 U11.G3 | length 988.6
  TopLayer - S1 (.GTL) w4.68: v1(1098.43,1129.92) U11.G3@1114.17,1145.67 ; U11.G3@1113.5,1144.99 U11.G3@1114.1,1144.99
  TopLayer - S1 (.GTL) w4.92: v1(954.92,508.65) U1.K9@970.7,524.43
  MidLayer2 - S3 (.G2) w4.68: v1(954.92,508.65) 963.17,500.4 997.92,500.4 1002.92,505.4 1002.92,605.4 1082.92,685.4 1082.92,810.4 1142.92,870.4 1142.92,905.4 1187.92,950.4 1187.92,1055.4 1202.92,1070.4 1202.92,1135.4 1197.92,1140.4 1187.92,1140.4 1182.92,1135.4 1182.92,1115.4 1177.92,1110.4 1117.92,1110.4 v1(1098.43,1129.92)
  BottomLayer - S8 (.GBL) w4.92: R36.2@954.92,470.4 R36.2@954.92,474.02 v1(954.92,508.65)
DDR_CKN: U1.K7 U11.D1 | length 944.2
  TopLayer - S1 (.GTL) w3.98: U1.K7@970.67,587.4 970.67,576.75 974.78,572.64 980.59,572.64 984.7,576.75 984.7,597.06 952.36,629.4 813.92,629.4 721.92,721.4 721.92,894.4 812.92,985.4 972.36,985.4 1023.92,1036.96 1023.92,1078.45 U11.D1@1019.68,1082.68
DDR_CSN: U1.L2 U11.H2 | length 940.2
  TopLayer - S1 (.GTL) w4.92: U1.L2@939.17,744.9 923.3,760.77 923.3,802.4 926.3,805.4 939.92,805.4 942.92,808.4 942.92,817.4 939.92,820.4 917.92,820.4 907.92,810.4 767.92,810.4 762.92,815.4 762.92,820.65 767.92,825.65 902.92,825.65 912.67,835.4 959.92,835.4 962.92,832.4 962.92,813.4 965.92,810.4 1017.92,810.4 1080.42,872.9 1080.42,917.9 1161.44,998.92 1161.44,1098.42 U11.H2@1145.68,1114.18
DDR_D0: U1.E3 U11.M3 | length 918.3
  TopLayer - S1 (.GTL) w4.92: U1.E3@1128.17,713.4 v1(1143.92,697.65) ; U11.M3@1271.65,1145.67 v1(1287.4,1129.92)
  MidLayer2 - S3 (.G2) w4.68: v1(1143.92,697.65) 1212.92,697.65 1217.92,692.65 1217.92,675.4 1212.92,670.4 1122.92,670.4 1117.92,665.4 1117.92,645.4 1122.92,640.4 1207.92,640.4 1337.92,770.4 1337.92,1065.4 1287.42,1115.9 v1(1287.4,1129.92)
DDR_D1: U1.F7 U11.M4 | length 918.7
  TopLayer - S1 (.GTL) w4.92: U1.F7@1096.67,587.4 v1(1112.42,571.65) ; U11.M4@1271.65,1177.17 v1(1287.4,1161.42)
  MidLayer2 - S3 (.G2) w4.68: v1(1112.42,571.65) 1096.68,555.91 1096.68,533.65 1087.44,524.41 1056.29,524.41 1042.57,524.39 1018.17,548.79 1018.17,595.65 1096.43,673.91 1096.43,803.91 1182.92,890.4 1182.92,915.4 1202.92,935.4 1202.92,1035.4 1240.16,1072.64 1240.16,1136.4 1249.4,1145.64 1271.66,1145.64 v1(1287.4,1161.42)
DDR_D2: U1.F2 U11.N1 | length 918.8
  TopLayer - S1 (.GTL) w4.92: U1.F2@1096.67,744.9 1112.44,729.13 1112.44,710.4 1112.54,710.3 1112.54,691.03 1122.92,680.65 1248.17,680.65 1307.92,740.4 1347.92,740.4 1352.92,745.4 1352.92,990.4 1347.92,995.4 1337.92,995.4 1332.92,990.4 1332.92,905.4 1327.92,900.4 1292.92,900.4 1287.92,905.4 1287.92,950.4 1303.16,965.64 U11.N1@1303.15,1082.68
DDR_D3: U1.F8 U11.N2 | length 918.1
  TopLayer - S1 (.GTL) w4.92: U1.F8@1096.67,555.9 v1(1112.42,540.15) ; U11.N2@1303.15,1114.17 1318.89,1098.45 1318.89,951.37 v1(1307.92,940.4)
  BottomLayer - S8 (.GBL) w4.92: v1(1112.42,540.15) 1128.16,524.41 1151.93,524.41 1159.66,532.14 1159.66,555.4 1172.92,568.66 1172.92,600.4 1167.92,605.4 1132.92,605.4 1127.92,610.4 1127.92,620.4 1132.92,625.4 1167.92,625.4 1172.92,630.4 1172.92,640.4 1167.92,645.4 1132.92,645.4 1127.92,650.4 1127.92,657.9 1132.92,662.9 1155.42,662.9 1187.92,695.4 1247.92,695.4 1307.92,755.4 v1(1307.92,940.4)
DDR_D4: U1.H3 U11.N3 | length 917.7
  TopLayer - S1 (.GTL) w4.92: U1.H3@1033.67,713.4 1033.67,649.65 1062.92,620.4 1292.92,620.4 1327.92,655.4 v1(1327.92,695.4) ; U11.N3@1303.15,1145.67 v1(1318.9,1129.92)
  MidLayer2 - S3 (.G2) w4.68: v1@1318.92,1129.4 1367.92,1080.4 1367.92,735.4 v1(1327.92,695.4)
DDR_D5: U1.H8 U11.N4 | length 917.3
  TopLayer - S1 (.GTL) w4.92: U1.H8@1033.67,555.9 v1(1049.42,540.15) ; U11.N4@1303.15,1177.17 v1(1318.9,1161.42)
  MidLayer2 - S3 (.G2) w4.68: v1(1049.42,540.15) 1032.92,556.65 1032.92,585.4 1067.92,620.4 1212.92,620.4 1352.92,760.4 1352.92,1070.4 1303.16,1120.16 1303.16,1145.64 v1(1318.9,1161.42)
